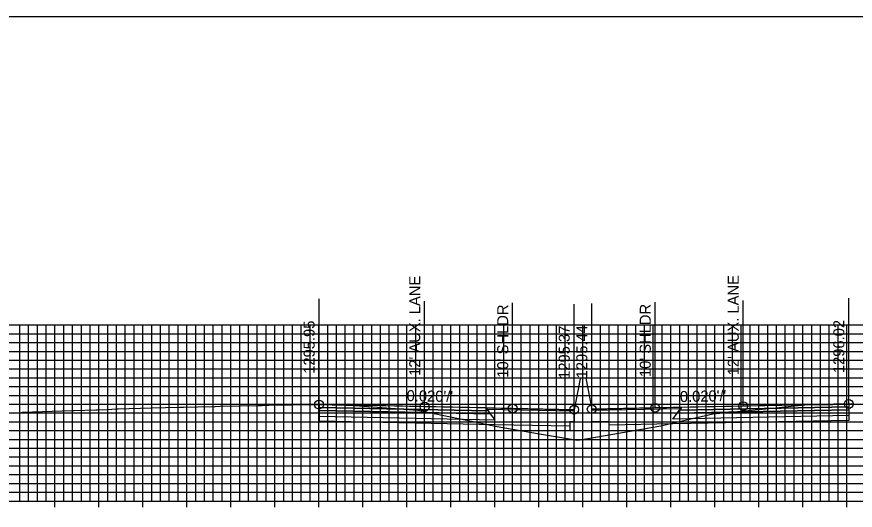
# Model space of a CAD drawing. Extents: x 674939 to 678919, y 750652 to 765176.
# Drawn here: x 678674.2 to 678769.5, y 754766.5 to 754822.6 of the extents above; entities that cross this region are included whole.
import ezdxf

# ---------------------------------------------------------------- set-up
doc = ezdxf.new("R2010")
doc.units = 0
for name, color, linetype in [('R_Alt Surface', 7, 'Continuous'), ('R_Axis', 7, 'Continuous'), ('R_Exist Surface', 7, 'Continuous'), ('R_Fin Surface', 7, 'Continuous'), ('R_Grid', 7, 'Continuous'), ('R_No Plot', 7, 'Continuous'), ('R_Proposed Road', 7, 'Continuous'), ('R_Xsect Elev', 7, 'Continuous'), ('R_Xsect Slope', 7, 'Continuous')]:
    doc.layers.add(name, color=color, linetype=linetype)

msp = doc.modelspace()

# ---------------------------------------------------------------- linework, layer by layer
at = {"layer": 'R_Alt Surface'}
for points in [[(678768.741, 754778.243), (678768.741, 754777.913), (678749.241, 754777.523), (678749.491, 754777.858)], [(678708.544, 754778.172), (678708.544, 754777.842), (678728.044, 754777.452), (678727.794, 754777.787)], [(678708.544, 754777.842), (678708.544, 754777.182), (678728.544, 754776.782), (678728.044, 754777.452)], [(678768.741, 754777.913), (678768.741, 754777.253), (678748.741, 754776.853), (678749.241, 754777.523)]]:
    msp.add_lwpolyline(points, close=True, dxfattribs=at)
for points in [[(678708.544, 754777.182), (678708.544, 754776.642), (678728.544, 754776.242), (678737.033, 754776.072)], [(678768.741, 754777.253), (678768.741, 754776.713), (678748.741, 754776.313), (678741.533, 754776.169)]]:
    msp.add_lwpolyline(points, dxfattribs=at)
at = {"layer": 'R_Axis'}
for p, q in [((678678.533, 754766.851), (678678.533, 754768.251)), ((678683.533, 754766.851), (678683.533, 754768.251)), ((678688.533, 754766.851), (678688.533, 754768.251)), ((678693.533, 754766.851), (678693.533, 754768.251)), ((678698.533, 754766.851), (678698.533, 754768.251)), ((678703.533, 754766.851), (678703.533, 754768.251)), ((678708.533, 754766.851), (678708.533, 754768.251)), ((678713.533, 754766.851), (678713.533, 754768.251)), ((678718.533, 754766.851), (678718.533, 754768.251)), ((678723.533, 754766.851), (678723.533, 754768.251)), ((678728.533, 754766.851), (678728.533, 754768.251)), ((678733.533, 754766.851), (678733.533, 754768.251)), ((678738.533, 754766.851), (678738.533, 754768.251)), ((678743.533, 754766.851), (678743.533, 754768.251)), ((678748.533, 754766.851), (678748.533, 754768.251)), ((678753.533, 754766.851), (678753.533, 754768.251)), ((678758.533, 754766.851), (678758.533, 754768.251)), ((678763.533, 754766.851), (678763.533, 754768.251)), ((678768.533, 754766.851), (678768.533, 754768.251)), ((678638.533, 754767.551), (678838.533, 754767.551))]:
    msp.add_line(p, q, dxfattribs=at)
at = {"layer": 'R_Exist Surface'}
msp.add_lwpolyline([(678673.822, 754777.515), (678674.717, 754777.621), (678674.834, 754777.627), (678680.482, 754777.841), (678680.717, 754777.848), (678683.164, 754777.905), (678683.328, 754777.908), (678684.458, 754777.947), (678684.517, 754777.949), (678684.545, 754777.951), (678684.995, 754777.978), (678685.003, 754777.978), (678685.493, 754778.007), (678685.729, 754778.013), (678689.494, 754778.126), (678692.692, 754778.194), (678693.13, 754778.202), (678696.329, 754778.272), (678696.705, 754778.266), (678696.729, 754778.268), (678697.294, 754778.33), (678701.62, 754778.401), (678702.084, 754778.41), (678702.836, 754778.433), (678708.316, 754778.499), (678708.544, 754778.502), (678708.555, 754778.502), (678708.717, 754778.504), (678710.034, 754778.461), (678710.117, 754778.457), (678710.153, 754778.458), (678711.47, 754778.434), (678711.579, 754778.431), (678712.519, 754778.401), (678712.552, 754778.408), (678713.138, 754778.362), (678719.773, 754777.853), (678726.444, 754776.495), (678728.556, 754776.066), (678733.582, 754775.201), (678737.922, 754774.453), (678738.209, 754774.503), (678747.378, 754776.088), (678748.831, 754776.431), (678753.283, 754777.441), (678758.117, 754777.916), (678760.47, 754778.144), (678762.207, 754778.311), (678764.528, 754778.541), (678764.673, 754778.504), (678764.797, 754778.474), (678766.335, 754778.512), (678766.937, 754778.526), (678767.776, 754778.535), (678768.258, 754778.544), (678768.677, 754778.562), (678768.738, 754778.573), (678768.741, 754778.573), (678769.16, 754778.591), (678771.537, 754778.546)], dxfattribs=at)
at = {"layer": 'R_Fin Surface'}
for points in [[(678737.533, 754777.922), (678730.544, 754778.062), (678720.544, 754778.262), (678708.544, 754778.502)], [(678768.741, 754778.573), (678756.741, 754778.333), (678746.741, 754778.133), (678739.533, 754777.989)]]:
    msp.add_lwpolyline(points, dxfattribs=at)
for points in [[(678708.544, 754778.502), (678708.544, 754778.172), (678727.794, 754777.787), (678727.544, 754778.122)], [(678768.741, 754778.573), (678768.741, 754778.243), (678749.491, 754777.858), (678749.741, 754778.193)], [(678727.544, 754778.122), (678737.533, 754777.922), (678737.537, 754777.764), (678727.663, 754777.962)], [(678749.622, 754778.033), (678739.533, 754777.832), (678739.533, 754777.989), (678749.741, 754778.193)]]:
    msp.add_lwpolyline(points, close=True, dxfattribs=at)
at = {"layer": 'R_Grid'}
for p, q in [((678638.533, 754787.551), (678838.533, 754787.551)), ((678674.533, 754767.551), (678674.533, 754787.551)), ((678675.533, 754767.551), (678675.533, 754787.551)), ((678676.533, 754767.551), (678676.533, 754787.551)), ((678677.533, 754767.551), (678677.533, 754787.551)), ((678678.533, 754767.551), (678678.533, 754787.551)), ((678679.533, 754767.551), (678679.533, 754787.551)), ((678680.533, 754767.551), (678680.533, 754787.551)), ((678681.533, 754767.551), (678681.533, 754787.551)), ((678682.533, 754767.551), (678682.533, 754787.551)), ((678683.533, 754767.551), (678683.533, 754787.551)), ((678684.533, 754767.551), (678684.533, 754787.551)), ((678685.533, 754767.551), (678685.533, 754787.551)), ((678686.533, 754767.551), (678686.533, 754787.551)), ((678687.533, 754767.551), (678687.533, 754787.551)), ((678688.533, 754767.551), (678688.533, 754787.551)), ((678689.533, 754767.551), (678689.533, 754787.551)), ((678690.533, 754767.551), (678690.533, 754787.551)), ((678691.533, 754767.551), (678691.533, 754787.551)), ((678692.533, 754767.551), (678692.533, 754787.551)), ((678693.533, 754767.551), (678693.533, 754787.551)), ((678694.533, 754767.551), (678694.533, 754787.551)), ((678695.533, 754767.551), (678695.533, 754787.551)), ((678696.533, 754767.551), (678696.533, 754787.551)), ((678697.533, 754767.551), (678697.533, 754787.551)), ((678698.533, 754767.551), (678698.533, 754787.551)), ((678699.533, 754767.551), (678699.533, 754787.551)), ((678700.533, 754767.551), (678700.533, 754787.551)), ((678701.533, 754767.551), (678701.533, 754787.551)), ((678702.533, 754767.551), (678702.533, 754787.551)), ((678703.533, 754767.551), (678703.533, 754787.551)), ((678704.533, 754767.551), (678704.533, 754787.551)), ((678705.533, 754767.551), (678705.533, 754787.551)), ((678706.533, 754767.551), (678706.533, 754787.551)), ((678707.533, 754767.551), (678707.533, 754787.551)), ((678708.533, 754767.551), (678708.533, 754787.551)), ((678709.533, 754767.551), (678709.533, 754787.551)), ((678710.533, 754767.551), (678710.533, 754787.551)), ((678711.533, 754767.551), (678711.533, 754787.551)), ((678712.533, 754767.551), (678712.533, 754787.551)), ((678713.533, 754767.551), (678713.533, 754787.551)), ((678714.533, 754767.551), (678714.533, 754787.551)), ((678715.533, 754767.551), (678715.533, 754787.551)), ((678716.533, 754767.551), (678716.533, 754787.551)), ((678717.533, 754767.551), (678717.533, 754787.551)), ((678718.533, 754767.551), (678718.533, 754787.551)), ((678719.533, 754767.551), (678719.533, 754787.551)), ((678720.533, 754767.551), (678720.533, 754787.551)), ((678721.533, 754767.551), (678721.533, 754787.551)), ((678722.533, 754767.551), (678722.533, 754787.551)), ((678723.533, 754767.551), (678723.533, 754787.551)), ((678724.533, 754767.551), (678724.533, 754787.551)), ((678725.533, 754767.551), (678725.533, 754787.551)), ((678726.533, 754767.551), (678726.533, 754787.551)), ((678727.533, 754767.551), (678727.533, 754787.551)), ((678728.533, 754767.551), (678728.533, 754787.551)), ((678729.533, 754767.551), (678729.533, 754787.551)), ((678730.533, 754767.551), (678730.533, 754787.551)), ((678731.533, 754767.551), (678731.533, 754787.551)), ((678732.533, 754767.551), (678732.533, 754787.551)), ((678733.533, 754767.551), (678733.533, 754787.551)), ((678734.533, 754767.551), (678734.533, 754787.551)), ((678735.533, 754767.551), (678735.533, 754787.551)), ((678736.533, 754767.551), (678736.533, 754787.551)), ((678737.533, 754767.551), (678737.533, 754787.551)), ((678738.533, 754767.551), (678738.533, 754787.551)), ((678739.533, 754767.551), (678739.533, 754787.551)), ((678740.533, 754767.551), (678740.533, 754787.551)), ((678741.533, 754767.551), (678741.533, 754787.551)), ((678742.533, 754767.551), (678742.533, 754787.551)), ((678743.533, 754767.551), (678743.533, 754787.551)), ((678744.533, 754767.551), (678744.533, 754787.551)), ((678745.533, 754767.551), (678745.533, 754787.551)), ((678746.533, 754767.551), (678746.533, 754787.551)), ((678747.533, 754767.551), (678747.533, 754787.551)), ((678748.533, 754767.551), (678748.533, 754787.551)), ((678749.533, 754767.551), (678749.533, 754787.551)), ((678750.533, 754767.551), (678750.533, 754787.551)), ((678751.533, 754767.551), (678751.533, 754787.551)), ((678752.533, 754767.551), (678752.533, 754787.551)), ((678753.533, 754767.551), (678753.533, 754787.551)), ((678754.533, 754767.551), (678754.533, 754787.551)), ((678755.533, 754767.551), (678755.533, 754787.551)), ((678756.533, 754767.551), (678756.533, 754787.551)), ((678757.533, 754767.551), (678757.533, 754787.551)), ((678758.533, 754767.551), (678758.533, 754787.551)), ((678759.533, 754767.551), (678759.533, 754787.551)), ((678760.533, 754767.551), (678760.533, 754787.551)), ((678761.533, 754767.551), (678761.533, 754787.551)), ((678762.533, 754767.551), (678762.533, 754787.551)), ((678763.533, 754767.551), (678763.533, 754787.551)), ((678764.533, 754767.551), (678764.533, 754787.551)), ((678765.533, 754767.551), (678765.533, 754787.551)), ((678766.533, 754767.551), (678766.533, 754787.551)), ((678767.533, 754767.551), (678767.533, 754787.551)), ((678768.533, 754767.551), (678768.533, 754787.551)), ((678638.533, 754786.551), (678838.533, 754786.551)), ((678638.533, 754785.551), (678838.533, 754785.551)), ((678638.533, 754784.551), (678838.533, 754784.551)), ((678638.533, 754783.551), (678838.533, 754783.551)), ((678638.533, 754782.551), (678838.533, 754782.551)), ((678638.533, 754781.551), (678838.533, 754781.551)), ((678638.533, 754780.551), (678838.533, 754780.551)), ((678638.533, 754779.551), (678838.533, 754779.551)), ((678638.533, 754778.551), (678838.533, 754778.551)), ((678638.533, 754777.551), (678838.533, 754777.551)), ((678638.533, 754776.551), (678838.533, 754776.551)), ((678638.533, 754775.551), (678838.533, 754775.551)), ((678638.533, 754774.551), (678838.533, 754774.551)), ((678638.533, 754773.551), (678838.533, 754773.551)), ((678638.533, 754772.551), (678838.533, 754772.551)), ((678638.533, 754771.551), (678838.533, 754771.551)), ((678638.533, 754770.551), (678838.533, 754770.551)), ((678638.533, 754769.551), (678838.533, 754769.551)), ((678638.533, 754768.551), (678838.533, 754768.551)), ((678638.533, 754767.551), (678838.533, 754767.551))]:
    msp.add_line(p, q, dxfattribs=at)
at = {"layer": 'R_No Plot'}
msp.add_lwpolyline([(678578.533, 754602.551), (678918.533, 754602.551), (678918.533, 754822.551), (678578.533, 754822.551)], close=True, dxfattribs=at)
for centre in [(678708.544, 754778.502), (678720.544, 754778.262), (678730.544, 754778.062), (678737.533, 754777.922), (678739.533, 754777.989), (678746.741, 754778.133), (678756.741, 754778.333), (678768.741, 754778.573)]:
    msp.add_circle(centre, 0.5, dxfattribs=at)
at = {"layer": 'R_Proposed Road'}
for points in [[(678738.203, 754781.422), (678737.533, 754777.922)], [(678738.863, 754781.489), (678738.863, 754781.489), (678738.203, 754781.489), (678738.203, 754781.422)], [(678738.863, 754781.489), (678739.533, 754777.989)], [(678737.533, 754777.922), (678737.533, 754776.547), (678737.033, 754776.547), (678737.033, 754775.547), (678741.533, 754775.547), (678741.533, 754776.547), (678739.533, 754776.547), (678739.533, 754777.989)]]:
    msp.add_lwpolyline(points, dxfattribs=at)
at = {"layer": 'R_Xsect Elev'}
for p, q in [((678708.544, 754778.502), (678708.544, 754790.502)), ((678720.544, 754778.262), (678720.544, 754790.262)), ((678730.544, 754778.062), (678730.544, 754790.062)), ((678737.533, 754777.922), (678737.533, 754789.922)), ((678739.533, 754777.989), (678739.533, 754789.989)), ((678746.741, 754778.133), (678746.741, 754790.133)), ((678756.741, 754778.333), (678756.741, 754790.333)), ((678768.741, 754778.573), (678768.741, 754790.573))]:
    msp.add_line(p, q, dxfattribs=at)

# ---------------------------------------------------------------- texts
for s, p in [("12' AUX. LANE", (678720.044, 754781.762)), ("12' AUX. LANE", (678756.241, 754781.833)), ("10' SHLDR", (678730.044, 754781.562)), ("10' SHLDR", (678746.241, 754781.633)), ('1295.95', (678708.044, 754782.002)), ('1296.02', (678768.241, 754782.073)), ('1295.37', (678737.033, 754781.422)), ('1295.44', (678739.033, 754781.489))]:
    msp.add_text(s, height=1.25, rotation=90, dxfattribs=at).set_placement(p)
at = {"layer": 'R_Xsect Slope'}
for rotation, p in [(358.85424, (678718.488, 754778.903)), (1.14576, (678749.563, 754778.789))]:
    msp.add_text("0.020'/'", height=1.25, rotation=rotation, dxfattribs=at).set_placement(p)

doc.saveas('drawing.dxf')
